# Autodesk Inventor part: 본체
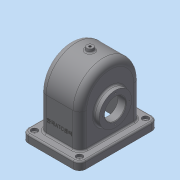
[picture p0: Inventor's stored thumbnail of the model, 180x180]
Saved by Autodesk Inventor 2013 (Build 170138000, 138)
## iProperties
Created: 2016-10
Part Number: 본체
Material: 일반
Document SubType Name: Modeling
Designer: Administrator
Density: 1 g/cm^3
Author: Administrator
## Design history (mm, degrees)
sketch "스케치2"
  geometry: L1 (-43, 75)-(43, 75); L2 (55, 63)-(55, -63); L3 (43, -75)-(-43, -75); L4 (-55, -63)-(-55, 63); A1 r 12 centre (-43, 63) between (-43, 75) and (-55, 63); A2 r 12 centre (43, 63) between (55, 63) and (43, 75); A3 r 12 centre (43, -63) between (43, -75) and (55, -63); A4 r 12 centre (-43, -63) between (-55, -63) and (-43, -75); 6 further points
  constraints: 8 end point, 8 point on circle, 8 tangent, 6 point on line, 4 centre point, 3 equal radius, 2 midpoint, 2 parallel, 1 horizontal, 1 horizontal alignment, 1 perpendicular, 1 vertical alignment
  dimensions: "d0" = 110 distance of point (-55, 75) point (55, 75); "d2" = 150 distance of point (55, 75) point (55, -75); "d3" = 12 radius of A1
extrude "돌출1" new body sketch "스케치2" distance "d4" = 15; taper "d5" = 0 deg
sketch "스케치3"
  geometry: L1 (15, -63)-(15, 63) reference; L2 (80, 58)-(15, 58); L3 (80, -58)-(15, -58); A1 r 58 centre (80, 0) between (80, -58) and (80, 58); 1 further point
  constraints: 4 end point, 2 perpendicular, 2 point on circle, 2 point on line, 2 tangent, 1 centre point, 1 horizontal alignment
  dimensions: "d6" = 116 diameter of A1; "d8" = 80 distance of point (0, 0) A1.centre
extrude "돌출2" join sketch "스케치3" stored distance "d9" = 77; taper "d10" = 0 deg
sketch "스케치4"
  geometry: L1 (15, 58)-(80, 58) reference; L2 (80, -58)-(15, -58) reference; L3 (15, 52)-(80, 52); L4 (80, -52)-(15, -52); L5 (15, 52)-(-29.084, 52); L6 (-29.084, 52)-(-29.084, -52); L7 (-29.084, -52)-(15, -52); A1 r 58 centre (80, 0) between (80, -58) and (80, 58) reference; A2 r 52 centre (80, 0) between (80, -52) and (80, 52); 1 further point
  constraints: 10 end point, 2 parallel, 2 point on circle, 1 centre point, 1 perpendicular, 2 other
  dimensions: "d11" = 6 distance between parallel lines of L1 L3
extrude "돌출3" cut sketch "스케치4" stored distance "d12" = 67; taper "d13" = 0 deg
sketch "스케치7"
  geometry: L1 (-33.5, 132)-(-33.5, 80) reference; L2 (-33.5, 80)-(-33.5, 0) reference; L3 (-74.821, 65)-(72.258, 65); L4 (-43.5, 65)-(-43.5, 102.5); L5 (-43.5, 102.5)-(-33.5, 102.5); L6 (-33.5, 104.747)-(-19.5, 93); L7 (-19.5, 93)-(-19.5, 65); L8 (-38.5, 138)-(-38.5, 80) reference; L9 (-33.5, 102.5)-(-33.5, 104.747); L10 (-43.5, 65)-(-19.5, 65); 1 further point
  constraints: 14 end point, 4 perpendicular, 4 point on line, 2 collinear
  dimensions: "d17" = 65 vertical distance of point (0, 0) L3.end; "d19" = 50 deg angle of L6 L7; "d20" = 24 distance between parallel lines of L4 L7; "d21" = 5 distance between parallel lines of L4 L8; "d22" = 75 diameter of L5 L3; "d23" = 56 diameter of L6.end L3
revolve "회전1" sketch "스케치7" stored, may be unused: angle "d24" = 90 deg
sketch "스케치8"
  geometry: C1 r 31 at (0, 65); 1 further point
  constraints: 1 centre point, 1 vertical alignment
  dimensions: "d25" = 62 diameter of C1; "d27" = 65 distance of point (0, 0) C1.centre
extrude "돌출4" join sketch "스케치8" distance "d28" = 10; taper "d29" = 0 deg
hole "구멍1" diameter "d32" = 40; stored, may be unused: countersink angle "d36" = 90 deg, drill point angle "d38" = 118 deg; dims "d30" = 10, "d31" = 10, "d33" = 6, "d34" = 4, "d35" = 2, "d37" = 8
node "작업 평면1"
sketch "스케치9"
  geometry: C1 r 6 at (0, 0); 1 further point
  constraints: 1 centre point, 1 coincident
  dimensions: "d40" = 12 diameter of C1
extrude "돌출5" join sketch "스케치9" stored distance "d42" = 10; taper "d43" = 10 deg
hole "구멍2" diameter "d46" = 4.459; stored, may be unused: countersink angle "d50" = 90 deg, drill point angle "d52" = 118 deg; dims "d44" = 10, "d45" = 10, "d47" = 30, "d48" = 4, "d49" = 2, "d51" = 30
sketch "스케치10"
  geometry: L1 (13.613, 28.602)-(63.387, 28.602); L2 (63.387, 28.602)-(63.387, 21.398); L3 (63.387, 21.398)-(13.613, 21.398); L4 (13.613, 21.398)-(13.613, 28.602); 4 further points
  constraints: 2 midpoint, 2 vertical alignment, 1 horizontal alignment, 2 other
  dimensions: "d53" = 40 distance of point (38.5, -15) point (38.5, 25)
feature "엠보싱1" sketch "스케치10" dims "d0" = 110, "d2" = 150, "d3" = 12, "d6" = 116, "d8" = 80, "d54" = 0.5, "d55" = 0
sketch "스케치11" dims "d56" = 58
  geometry: C1 r 37.5 at (0, 0) reference; 3 further points
  constraints: 2 vertical alignment, 1 coincident, 2 other
hole "구멍3" sketch "스케치11" at (0, 29) diameter "d58" = 2.459; stored, may be unused: countersink angle "d62" = 90 deg, drill point angle "d64" = 118 deg; dims "d59" = 6, "d60" = 4, "d61" = 2, "d63" = 8
sketch "스케치12" dims "d68" = 52
  geometry: C1 r 31 at (0, 0) reference; 3 further points
  constraints: 2 vertical alignment, 1 coincident, 2 other
hole "구멍4" sketch "스케치12" at (0, 26) diameter "d70" = 2.459; stored, may be unused: countersink angle "d74" = 90 deg, drill point angle "d76" = 118 deg; dims "d71" = 6, "d72" = 4, "d73" = 2, "d75" = 8
sketch "스케치13"
  geometry: A1 r 12 centre (-43, 63) between (-43, 75) and (-55, 63) reference; A2 r 12 centre (43, 63) between (55, 63) and (43, 75) reference; A3 r 12 centre (43, -63) between (43, -75) and (55, -63) reference; A4 r 12 centre (-43, -63) between (-55, -63) and (-43, -75) reference; 1 further point
hole "구멍5" sketch "스케치13" at (-43, -63), (43, -63), (43, 63), (-43, 63) diameter "d80" = 5; stored, may be unused: countersink angle "d84" = 90 deg, drill point angle "d86" = 118 deg; dims "d81" = 6, "d82" = 12, "d83" = 5, "d85" = 8
fillet "모깎기1" dims "d87" = 8
fillet "모깎기2" dims "d88" = 13
fillet "모깎기3" dims "d89" = 3
fillet "모깎기4" dims "d90" = 3
fillet "모깎기5" dims "d91" = 3
fillet "모깎기6" dims "d92" = 3
fillet "모깎기7" dims "d93" = 3
chamfer "모따기1" distance "d94" = 1; stored, may be unused: second distance "d95" = 2, angle "d96" = 45 deg
node "솔리드1"
pattern_circular "원형 패턴1" dims angle "d66" = 360 deg
pattern_circular "원형 패턴2" dims angle "d78" = 360 deg
other parameters: "d39" = 144
